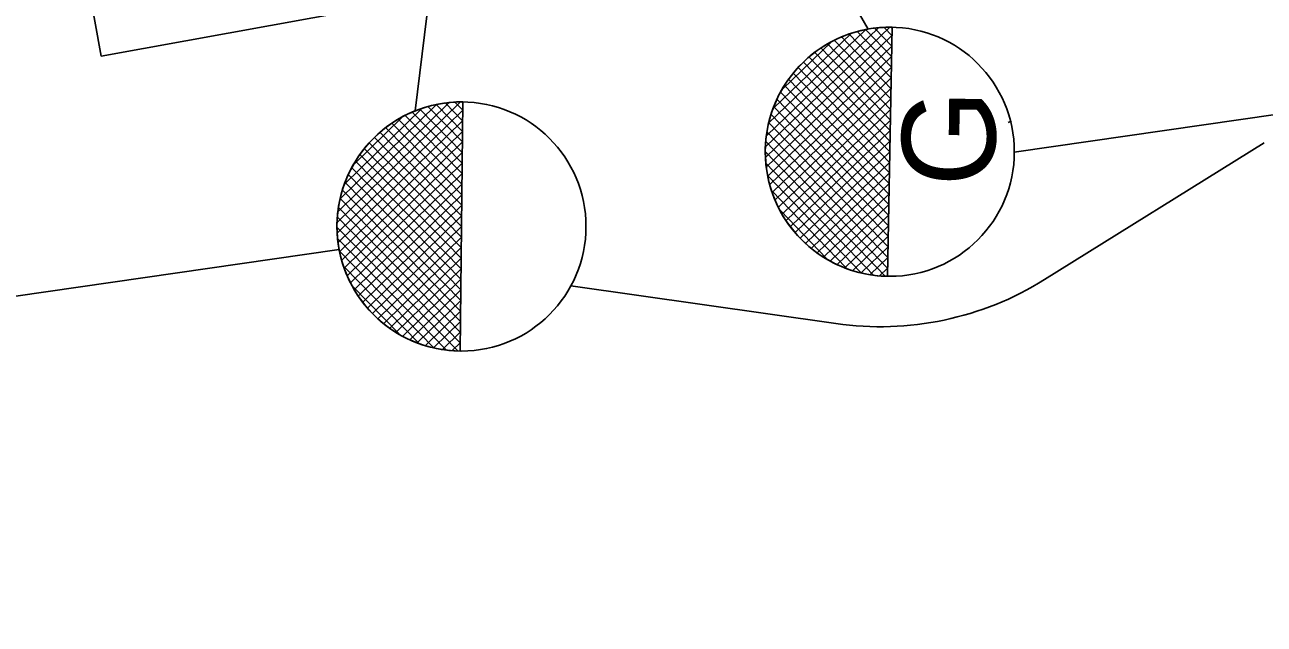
# Model space of a CAD drawing. Extents: x 584850 to 602551, y 145475 to 158627.
# Drawn here: x 586082.36 to 586122.18, y 156296.67 to 156315.92 of the extents above; entities that cross this region are included whole.
import ezdxf

# ---------------------------------------------------------------- set-up
doc = ezdxf.new("R2010")
doc.units = 0
doc.layers.add('Default', color=7, linetype='Continuous')

msp = doc.modelspace()

# ---------------------------------------------------------------- linework, layer by layer
at = {"layer": 'Default'}
for p, q in [((586109.46, 156315.781), (586107.152, 156319.755)), ((586094.901, 156313.155), (586095.472, 156317.78)), ((586110.078, 156307.842), (586110.228, 156315.841)), ((586110.183, 156315.84), (586110.227, 156315.797)), ((586110.148, 156315.836), (586106.162, 156311.997)), ((586110.223, 156315.575), (586106.17, 156311.671)), ((586109.777, 156315.811), (586106.201, 156312.368)), ((586109.37, 156315.753), (586106.259, 156312.756)), ((586108.909, 156315.642), (586106.417, 156313.243)), ((586108.612, 156315.517), (586110.191, 156313.878)), ((586108.847, 156315.619), (586110.197, 156314.217)), ((586109.111, 156315.69), (586110.204, 156314.557)), ((586109.382, 156315.755), (586110.21, 156314.896)), ((586109.668, 156315.804), (586110.216, 156315.235)), ((586109.982, 156315.825), (586110.223, 156315.575)), ((586110.216, 156315.235), (586106.187, 156311.354)), ((586108.29, 156315.38), (586106.71, 156313.857)), ((586107.952, 156315.165), (586110.172, 156312.86)), ((586108.157, 156315.298), (586110.178, 156313.199)), ((586108.376, 156315.416), (586110.185, 156313.538)), ((586110.21, 156314.896), (586106.242, 156311.074)), ((586107.387, 156314.713), (586110.153, 156311.842)), ((586107.564, 156314.876), (586110.159, 156312.181)), ((586107.747, 156315.032), (586110.165, 156312.521)), ((586110.204, 156314.557), (586106.296, 156310.793)), ((586107.061, 156314.36), (586110.14, 156311.163)), ((586107.211, 156314.55), (586110.146, 156311.502)), ((586110.197, 156314.217), (586106.383, 156310.543)), ((586110.191, 156313.878), (586106.475, 156310.299)), ((586106.77, 156313.97), (586110.127, 156310.484)), ((586106.913, 156314.167), (586110.134, 156310.824)), ((586106.534, 156313.523), (586110.115, 156309.806)), ((586110.185, 156313.538), (586106.575, 156310.062)), ((586106.652, 156313.747), (586110.121, 156310.145)), ((586096.355, 156313.437), (586092.4, 156309.566)), ((586096.432, 156313.176), (586092.41, 156309.24)), ((586095.984, 156313.409), (586092.436, 156309.938)), ((586095.578, 156313.347), (586092.491, 156310.326)), ((586095.117, 156313.233), (586092.645, 156310.814)), ((586094.821, 156313.106), (586096.414, 156311.479)), ((586095.056, 156313.21), (586096.417, 156311.819)), ((586095.319, 156313.283), (586096.421, 156312.158)), ((586095.59, 156313.35), (586096.424, 156312.497)), ((586095.876, 156313.401), (586096.428, 156312.837)), ((586096.189, 156313.424), (586096.432, 156313.176)), ((586096.349, 156305.443), (586096.435, 156313.443)), ((586096.39, 156313.441), (586096.434, 156313.398)), ((586106.431, 156313.284), (586110.108, 156309.466)), ((586110.178, 156313.199), (586106.701, 156309.85)), ((586096.428, 156312.837), (586092.43, 156308.924)), ((586094.501, 156312.966), (586092.933, 156311.431)), ((586094.164, 156312.748), (586096.403, 156310.461)), ((586094.368, 156312.883), (586096.406, 156310.8)), ((586094.586, 156313.003), (586096.41, 156311.14)), ((586106.262, 156312.767), (586110.095, 156308.788)), ((586106.347, 156313.026), (586110.102, 156309.127)), ((586110.172, 156312.86), (586106.826, 156309.637)), ((586114.062, 156312.826), (586113.959, 156312.781)), ((586096.424, 156312.497), (586092.487, 156308.644)), ((586093.603, 156312.292), (586096.392, 156309.443)), ((586093.778, 156312.456), (586096.395, 156309.783)), ((586093.96, 156312.614), (586096.399, 156310.122)), ((586106.216, 156312.469), (586110.089, 156308.448)), ((586110.165, 156312.521), (586106.966, 156309.438)), ((586096.421, 156312.158), (586092.544, 156308.364)), ((586093.28, 156311.936), (586096.384, 156308.764)), ((586093.428, 156312.128), (586096.388, 156309.104)), ((586106.172, 156312.169), (586110.083, 156308.109)), ((586110.159, 156312.181), (586107.121, 156309.255)), ((586122.182, 156312.132), (586115.123, 156307.735)), ((586096.417, 156311.819), (586092.632, 156308.114)), ((586096.414, 156311.479), (586092.727, 156307.871)), ((586092.992, 156311.544), (586096.377, 156308.086)), ((586093.134, 156311.743), (586096.381, 156308.425)), ((586106.166, 156311.829), (586110.002, 156307.847)), ((586106.175, 156311.474), (586109.634, 156307.883)), ((586110.153, 156311.842), (586107.276, 156309.071)), ((586110.146, 156311.502), (586107.451, 156308.906)), ((586092.759, 156311.096), (586096.37, 156307.407)), ((586096.41, 156311.14), (586092.829, 156307.635)), ((586092.876, 156311.32), (586096.373, 156307.746)), ((586110.14, 156311.163), (586107.636, 156308.751)), ((586092.659, 156310.855), (586096.366, 156307.067)), ((586096.406, 156310.8), (586092.956, 156307.423)), ((586106.245, 156311.055), (586109.225, 156307.961)), ((586110.134, 156310.824), (586107.82, 156308.595)), ((586092.494, 156310.337), (586096.359, 156306.389)), ((586092.576, 156310.597), (586096.362, 156306.728)), ((586096.403, 156310.461), (586093.082, 156307.211)), ((586106.368, 156310.582), (586108.747, 156308.112)), ((586110.127, 156310.484), (586108.031, 156308.465)), ((586092.45, 156310.038), (586096.355, 156306.049)), ((586096.399, 156310.122), (586093.224, 156307.014)), ((586106.638, 156309.955), (586108.128, 156308.409)), ((586110.121, 156310.145), (586108.246, 156308.339)), ((586092.409, 156309.738), (586096.352, 156305.71)), ((586096.395, 156309.783), (586093.38, 156306.832)), ((586110.115, 156309.806), (586108.466, 156308.218)), ((586092.405, 156309.398), (586096.273, 156305.448)), ((586096.392, 156309.443), (586093.537, 156306.65)), ((586096.388, 156309.104), (586093.713, 156306.486)), ((586110.108, 156309.466), (586108.715, 156308.125)), ((586110.102, 156309.127), (586108.964, 156308.031)), ((586092.417, 156309.044), (586095.905, 156305.48)), ((586096.384, 156308.764), (586093.9, 156306.332)), ((586110.095, 156308.788), (586109.236, 156307.959)), ((586092.491, 156308.625), (586095.495, 156305.555)), ((586096.381, 156308.425), (586094.085, 156306.178)), ((586110.089, 156308.448), (586109.524, 156307.904)), ((586092.617, 156308.153), (586095.015, 156305.703)), ((586096.377, 156308.086), (586094.297, 156306.05)), ((586110.083, 156308.109), (586109.822, 156307.858)), ((586092.892, 156307.529), (586094.394, 156305.994)), ((586096.373, 156307.746), (586094.513, 156305.925)), ((586108.421, 156306.324), (586099.91, 156307.54)), ((586110.078, 156307.842), (586110.078, 156307.844)), ((586110.078, 156307.842), (586110.078, 156307.844)), ((586096.37, 156307.407), (586094.734, 156305.806)), ((586096.366, 156307.067), (586094.984, 156305.714)), ((586096.362, 156306.728), (586095.233, 156305.623)), ((586096.359, 156306.389), (586095.506, 156305.553)), ((586096.355, 156306.049), (586095.795, 156305.5)), ((586096.352, 156305.71), (586096.093, 156305.457)), ((586096.349, 156305.443), (586096.349, 156305.445)), ((586096.349, 156305.443), (586096.349, 156305.445))]:
    msp.add_line(p, q, dxfattribs=at)
msp.add_lwpolyline([(586084.811, 156314.916), (586081.215, 156334.739), (586102.861, 156338.665), (586106.456, 156318.842)], close=True, dxfattribs=at)
for points in [[(586114.153, 156311.827), (586193.73, 156323.301)], [(586009.051, 156296.672), (586092.461, 156308.699)]]:
    msp.add_lwpolyline(points, dxfattribs=at)
for centre in [(586110.153, 156311.842), (586096.392, 156309.443)]:
    msp.add_circle(centre, 4, dxfattribs=at)
for centre, radius, start, end in [((586110.153, 156311.842), 4, 88.9257, 268.9257), ((586096.392, 156309.443), 4, 89.3846, 269.3846), ((586109.836, 156316.223), 10, 261.8672, 301.9166)]:
    msp.add_arc(centre, radius, start, end, dxfattribs=at)

# ---------------------------------------------------------------- texts
msp.add_text('G', height=3, rotation=89.3623, dxfattribs=at).set_placement((586113.53, 156310.71))

doc.saveas('drawing.dxf')
